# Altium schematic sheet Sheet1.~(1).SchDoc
size A4; SheetNumber: 1; SheetTotal: 1
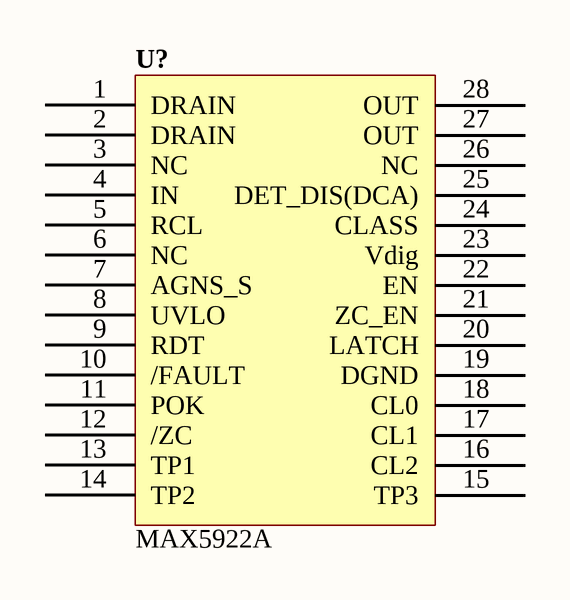
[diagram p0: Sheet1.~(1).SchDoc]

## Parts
U?  MAX5922A  [TSOP65P640-28]

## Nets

Not connected (* = marked no-connect by the designer): U? 1(DRAIN) 2(DRAIN) 3(NC) 4(IN) 5(RCL) 6(NC) 7(AGNS_S) 8(UVLO) 9(RDT) 10(/FAULT) 11(POK) 12(/ZC) 13(TP1) 14(TP2) 15(TP3) 16(CL2) 17(CL1) 18(CL0) 19(DGND) 20(LATCH) 21(ZC_EN) 22(EN) 23(Vdig) 24(CLASS) 25(DET_DIS(DCA)) 26(NC) 27(OUT) 28(OUT)

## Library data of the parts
U? = MAX5922: MAX5922A, PoE Controller; Max Input Voltage: mV; Max Output Current: mA; Aggiornato: NO; Costo: 0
